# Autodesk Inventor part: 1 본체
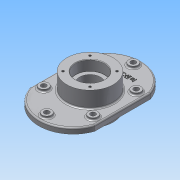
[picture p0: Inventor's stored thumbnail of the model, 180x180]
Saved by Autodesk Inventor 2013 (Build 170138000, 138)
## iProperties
Created: 2015-02
Part Number: 1 본체
Material: 알루미늄 6061
Document SubType Name: Modeling
Designer: ST5
Density: 2.71 g/cm^3
Mass: 1637.14 g
Surface Area: 925.885 cm^2
Volume: 604.109 cm^3
Author: ST5
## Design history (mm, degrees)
sketch "스케치1"
  geometry: L1 (-70, 60)-(70, 60); L2 (70, 60)-(70, -60); L3 (70, -60)-(-70, -60); L4 (-70, -60)-(-70, 60); A1 r 74 centre (0, 36) between (70, 60) and (-70, 60); A2 r 74 centre (0, -36) between (-70, -60) and (70, -60); 5 further points
  constraints: 8 end point, 6 point on circle, 3 vertical alignment, 2 centre point, 2 midpoint, 2 parallel, 1 horizontal, 1 horizontal alignment, 1 perpendicular
  dimensions: "d4" = 140 distance of L2.end L3.end; "d6" = 120 distance of L1.end L2.end; "d8" = 50 distance from line of point (0, 110) L1; "d9" = 50 distance from line of point (0, -110) L3
extrude "돌출1" new body sketch "스케치1" distance "d10" = 12; taper "d11" = 0 deg
sketch "스케치2"
  geometry: C1 r 50 at (0, 0); 1 further point
  constraints: 1 centre point, 1 coincident
  dimensions: "d12" = 100 diameter of C1
extrude "돌출2" join sketch "스케치2" distance "d14" = 35; taper "d15" = 0 deg
sketch "스케치3"
  geometry: C1 r 50 at (0, 0); 1 further point
  constraints: 1 centre point, 1 coincident
  dimensions: "d16" = 100 diameter of C1
extrude "돌출3" join sketch "스케치3" distance "d18" = 23; taper "d19" = 0 deg
sketch "스케치4"
  geometry: L1 (0, 47)-(0, -23); L2 (50, 47)-(-50, 47) reference; L3 (-50, -23)-(50, -23) reference; L4 (31, 47)-(31, 25); L5 (31, 25)-(22.5, 25); L6 (22.5, 25)-(22.5, -1); L7 (22.5, -1)-(31, -1); L8 (31, -1)-(31, -23); 2 further points
  constraints: 12 end point, 3 point on line, 2 collinear, 2 equal length, 2 midpoint, 2 perpendicular, 2 vertical, 1 coincident
  dimensions: "d20" = 62 diameter of L8 L1; "d22" = 45 diameter of L6 L1; "d23" = 22 distance of L4.start L4.end
revolve "회전1" sketch "스케치4" stored, may be unused: angle "d24" = 90 deg
sketch "스케치5"
  geometry: L1 (-70, 60)-(-70, -60) reference; L2 (70, -60)-(70, 60) reference; L3 (53, 56.976)-(53, -56.976); L4 (-53, -56.976)-(-53, 56.976); C1 r 50 at (0, 0) reference; C2 r 10 at (0, 93); C3 r 10 at (0, -93); C4 r 10 at (-53, 46.5); C5 r 10 at (53, 46.5); C6 r 10 at (53, -46.5); C7 r 10 at (-53, -46.5); A1 r 74 centre (0, 36) between (70, 60) and (-70, 60) reference; A2 r 74 centre (0, -36) between (-70, -60) and (70, -60) reference; A3 r 57 centre (0, 36) between (53, 56.976) and (-53, 56.976); A4 r 57 centre (0, -36) between (-53, -56.976) and (53, -56.976)
  constraints: 8 centre point, 6 point on circle, 5 equal radius, 4 end point, 4 point on line, 2 horizontal alignment, 1 vertical alignment, 3 other
  dimensions: "d25" = 17 distance between parallel lines of L1 L4; "d26" = 20 diameter of C2; "d28" = 46.5 vertical distance of C4.centre C2.centre; "d29" = 46.5 vertical distance of C7.centre C3.centre
extrude "돌출4" join sketch "스케치5" distance "d30" = 5; taper "d31" = 0 deg
sketch "스케치6"
  geometry: C1 r 10 at (0, 0) reference; C2 r 10 at (-53, 139.5) reference; C3 r 10 at (0, 93) reference; C4 r 10 at (-53, -46.5) reference; C5 r 10 at (-106, 0) reference; C6 r 10 at (-106, 93) reference; C7 r 5.5 at (-106, 93); C8 r 5.5 at (-53, 139.5); C9 r 5.5 at (0, 93); C10 r 5.5 at (0, 0); C11 r 5.5 at (-53, -46.5); C12 r 5.5 at (-106, 0); 1 further point
  constraints: 6 centre point, 6 coincident, 5 equal radius
  dimensions: "d32" = 11 diameter of C8
extrude "돌출5" cut sketch "스케치6" distance "d34" = 30; taper "d35" = 0 deg
sketch "스케치7"
  geometry: C1 r 31 at (0, 0) reference; C2 r 50 at (0, 0) reference; A1 r 41 centre (0, 0) between (-28.991, 28.991) and (28.991, 28.991); 2 further points
  constraints: 4 point on circle, 2 horizontal alignment, 2 vertical alignment, 1 centre point, 1 coincident
  dimensions: "d36" = 82 diameter of A1; "d38" = 90 deg dimension on C1.centre A1.end A1.start
hole "구멍1" sketch "스케치7" at (28.991, 28.991), (-28.991, 28.991), (-28.991, -28.991), (28.991, -28.991) diameter "d40" = 4.917; stored, may be unused: countersink angle "d44" = 90 deg, drill point angle "d46" = 118 deg; dims "d41" = 10, "d42" = 4, "d43" = 2, "d45" = 13
node "작업 평면1"
chamfer "모따기1" distance "d47" = 1; stored, may be unused: second distance "d48" = 2, angle "d49" = 45 deg
fillet "모깎기1" dims "d50" = 0.3
fillet "모깎기3" dims "d52" = 3
fillet "모깎기4" dims "d53" = 3
fillet "모깎기5" dims "d54" = 3
sketch "스케치8"
  geometry: C1 r 53 at (0, 0) reference; 1 further point
  constraints: 1 vertical alignment, 1 other
  dimensions: "d55" = 65 distance of C1.centre point (0, 65)
feature "엠보싱1" sketch "스케치8" dims "d4" = 140, "d6" = 120, "d8" = 50, "d9" = 50, "d20" = 62, "d22" = 45, "d23" = 22, "d56" = 1, "d57" = 0
node "솔리드1"
mirror "대칭1"
node "투영된 루프1"
node "투영된 루프2"
node "투영된 루프3"
node "투영된 루프4"
node "투영된 루프5"
